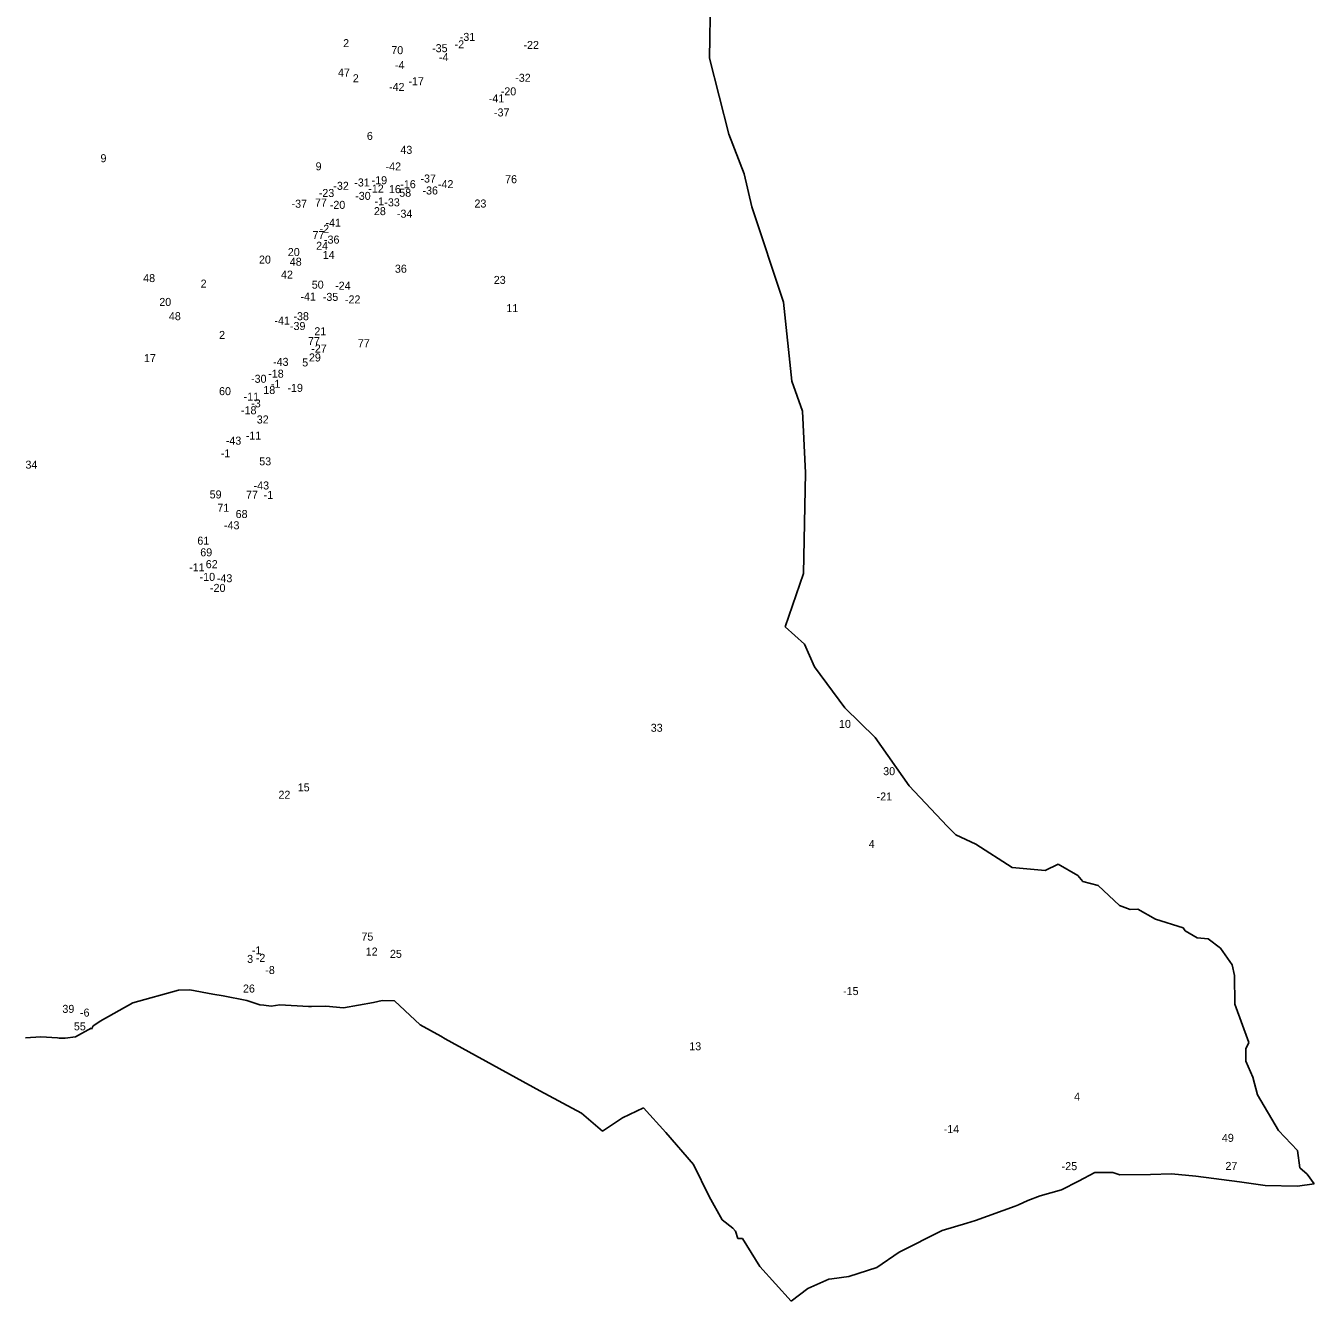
# Model space of a CAD drawing. Extents: x -774899 to -771684, y -969532 to -966391.
# Drawn here: x -773293 to -771684, y -969532 to -967940 of the extents above; entities that cross this region are included whole.
import ezdxf

# ---------------------------------------------------------------- set-up
doc = ezdxf.new("R2010")
doc.units = 0
doc.layers.add('Vrstva 13', color=7, linetype='Continuous')
doc.layers.add('Vrstva 24', color=7, linetype='Continuous')

msp = doc.modelspace()

# ---------------------------------------------------------------- linework, layer by layer
at = {"layer": 'Vrstva 13'}
for p, q in [((-772437.19, -967872.16), (-772439.45, -967979.8)), ((-772439.45, -967979.8), (-772415.04, -968074.78)), ((-772415.04, -968074.78), (-772396.05, -968124.53)), ((-772396.05, -968124.53), (-772386.56, -968165.69)), ((-772386.56, -968165.69), (-772346.77, -968284.64)), ((-772346.77, -968284.64), (-772336.37, -968383.23)), ((-772336.37, -968383.23), (-772323.26, -968420.77)), ((-772323.26, -968420.77), (-772319.31, -968497.55)), ((-772319.31, -968497.55), (-772321.8, -968623.5)), ((-772321.8, -968623.5), (-772344.62, -968690.22)), ((-772344.62, -968690.22), (-772320.66, -968711.7)), ((-772320.66, -968711.7), (-772308.23, -968739.97)), ((-772308.23, -968739.97), (-772270.03, -968791.08)), ((-772270.03, -968791.08), (-772232.5, -968828.16)), ((-772232.5, -968828.16), (-772190.02, -968888.54)), ((-772190.02, -968888.54), (-772142.32, -968938.74)), ((-772142.32, -968938.74), (-772131.7, -968949.82)), ((-772131.7, -968949.82), (-772106.6, -968961.35)), ((-772106.6, -968961.35), (-772061.17, -968990.75)), ((-772061.17, -968990.75), (-772019.8, -968994.14)), ((-772019.8, -968994.14), (-772003.76, -968986.22)), ((-772003.76, -968986.22), (-771979.34, -969000.46)), ((-771979.34, -969000.46), (-771973.01, -969008.15)), ((-771973.01, -969008.15), (-771953.57, -969013.13)), ((-771953.57, -969013.13), (-771926.9, -969038)), ((-771926.9, -969038), (-771913.79, -969042.98)), ((-771913.79, -969042.98), (-771904.07, -969042.52)), ((-771904.07, -969042.52), (-771882.14, -969054.96)), ((-771882.14, -969054.96), (-771847.55, -969066.04)), ((-771847.55, -969066.04), (-771845.06, -969069.44)), ((-771845.06, -969069.44), (-771829.91, -969078.49)), ((-771829.91, -969078.49), (-771816.35, -969079.62)), ((-771816.35, -969079.62), (-771800.98, -969091.38)), ((-771800.98, -969091.38), (-771786.51, -969111.96)), ((-771786.51, -969111.96), (-771783.57, -969125.53)), ((-771783.57, -969125.53), (-771783.12, -969161.03)), ((-773102.4, -969143.73), (-773159.41, -969159.5)), ((-773088.19, -969143.4), (-773102.4, -969143.73)), ((-773059.49, -969148.9), (-773088.19, -969143.4)), ((-773046.58, -969150.75), (-773059.49, -969148.9)), ((-773017.32, -969156.51), (-773046.58, -969150.75)), ((-773159.41, -969159.5), (-773200.39, -969182.61)), ((-773003.4, -969161.13), (-773017.32, -969156.51)), ((-773003.4, -969161.13), (-773000.97, -969161.95)), ((-773000.97, -969161.95), (-772995.77, -969162.34)), ((-772986.93, -969163.77), (-772995.77, -969162.34)), ((-772976.12, -969162.25), (-772986.93, -969163.77)), ((-772940.04, -969164.24), (-772976.12, -969162.25)), ((-772936.61, -969164.14), (-772940.04, -969164.24)), ((-772918.51, -969163.65), (-772936.61, -969164.14)), ((-772896.48, -969165.76), (-772918.51, -969163.65)), ((-772858.93, -969159.13), (-772896.48, -969165.76)), ((-772858.93, -969159.13), (-772848.29, -969156.56)), ((-772832.65, -969156.92), (-772848.29, -969156.56)), ((-772819.87, -969168.99), (-772832.65, -969156.92)), ((-772800.87, -969186.92), (-772819.87, -969168.99)), ((-771783.12, -969161.03), (-771765.49, -969209.2)), ((-773204.64, -969185.35), (-773209.22, -969188.39)), ((-773200.39, -969182.61), (-773204.64, -969185.35)), ((-773231.01, -969202.03), (-773211.56, -969191.33)), ((-773211.56, -969191.33), (-773211.3, -969192.34)), ((-773209.22, -969188.39), (-773211.3, -969192.34)), ((-772774.7, -969201.31), (-772800.87, -969186.92)), ((-772769.26, -969204.3), (-772774.7, -969201.31)), ((-773274.63, -969201.98), (-773293.46, -969203.4)), ((-773253.53, -969203.43), (-773274.63, -969201.98)), ((-773253.53, -969203.43), (-773251.7, -969203.67)), ((-773251.7, -969203.67), (-773245.61, -969203.86)), ((-773245.61, -969203.86), (-773243.99, -969203.61)), ((-773231.01, -969202.03), (-773243.99, -969203.61)), ((-772651.15, -969269.24), (-772769.26, -969204.3)), ((-771765.49, -969209.2), (-771769.33, -969217.11)), ((-771769.33, -969217.11), (-771769.33, -969232.49)), ((-771769.33, -969232.49), (-771760.52, -969252.39)), ((-771760.52, -969252.39), (-771754.64, -969274.32)), ((-772599.16, -969297.26), (-772651.15, -969269.24)), ((-771754.64, -969274.32), (-771728.63, -969318.87)), ((-772572.97, -969319.97), (-772599.16, -969297.26)), ((-772521.8, -969290.83), (-772547.95, -969303.03)), ((-772493.99, -969321.5), (-772521.8, -969290.83)), ((-772547.95, -969303.03), (-772572.97, -969319.97)), ((-772459.33, -969361.3), (-772493.99, -969321.5)), ((-771728.63, -969318.87), (-771704.96, -969344.14)), ((-771704.96, -969344.14), (-771702.02, -969365.51)), ((-772439.82, -969401.52), (-772459.33, -969361.3)), ((-771957.98, -969371.59), (-771978.38, -969382.13)), ((-771935.57, -969371.35), (-771957.98, -969371.59)), ((-771926.63, -969374.16), (-771935.57, -969371.35)), ((-771888.48, -969373.7), (-771926.63, -969374.16)), ((-771862.03, -969372.94), (-771888.48, -969373.7)), ((-771831.91, -969375.83), (-771862.03, -969372.94)), ((-771777.16, -969383.06), (-771831.91, -969375.83)), ((-771702.02, -969365.51), (-771692.86, -969373.32)), ((-771692.86, -969373.32), (-771683.86, -969385.69)), ((-771999.37, -969392.97), (-772026.03, -969400.57)), ((-771978.38, -969382.13), (-771999.37, -969392.97)), ((-771745.31, -969387.83), (-771777.16, -969383.06)), ((-771704.77, -969388.59), (-771745.31, -969387.83)), ((-771683.86, -969385.69), (-771704.77, -969388.59)), ((-772423.56, -969430.4), (-772439.82, -969401.52)), ((-772041.78, -969406.46), (-772053.37, -969411.59)), ((-772026.03, -969400.57), (-772041.78, -969406.46)), ((-772057.63, -969413.46), (-772107.14, -969431.33)), ((-772053.37, -969411.59), (-772057.63, -969413.46)), ((-772410.02, -969440.78), (-772423.56, -969430.4)), ((-772406.7, -969444.71), (-772410.02, -969440.78)), ((-772117.82, -969434.57), (-772148.52, -969443.89)), ((-772107.14, -969431.33), (-772117.82, -969434.57)), ((-772403.77, -969453.81), (-772406.7, -969444.71)), ((-772397.94, -969453.99), (-772403.77, -969453.81)), ((-772376.33, -969488.77), (-772397.94, -969453.99)), ((-772148.52, -969443.89), (-772202.27, -969470.71)), ((-772202.27, -969470.71), (-772230.16, -969490.12)), ((-772337.14, -969532.14), (-772376.33, -969488.77)), ((-772230.16, -969490.12), (-772265.25, -969501.24)), ((-772290.01, -969504.4), (-772316.56, -969516.18)), ((-772286.56, -969504.02), (-772290.01, -969504.4)), ((-772265.25, -969501.24), (-772286.56, -969504.02)), ((-772316.56, -969516.18), (-772337.14, -969532.14))]:
    msp.add_line(p, q, dxfattribs=at)

# ---------------------------------------------------------------- texts
at = {"layer": 'Vrstva 24'}
for s, p in [('2', (-772896.876, -967966.18)), ('-2', (-772757.63, -967967.65)), ('-31', (-772751.244, -967958.41)), ('-22', (-772671.66, -967968.44)), ('70', (-772836.725, -967974.95)), ('-35', (-772785.75, -967972.47)), ('-4', (-772777.156, -967983.68)), ('47', (-772903.321, -968002.92)), ('-4', (-772832.116, -967993.59)), ('2', (-772884.796, -968010.05)), ('-17', (-772815.344, -968013.8)), ('-32', (-772681.93, -968009.46)), ('-42', (-772839.566, -968020.91)), ('-41', (-772715.01, -968035.19)), ('-20', (-772700, -968026.4)), ('-37', (-772708.449, -968052.71)), ('6', (-772867.23, -968082.03)), ('43', (-772825.382, -968099.41)), ('9', (-773199.98, -968109.87)), ('9', (-772931.27, -968119.98)), ('-42', (-772843.886, -968120.18)), ('-32', (-772909.14, -968144.34)), ('-31', (-772882.994, -968140.17)), ('-12', (-772865.474, -968147.87)), ('-19', (-772861.268, -968137.36)), ('16', (-772839.664, -968148.5)), ('-16', (-772825.508, -968142.31)), ('-37', (-772800.319, -968135.22)), ('-42', (-772778.466, -968142.27)), ('76', (-772694.568, -968136.11)), ('77', (-772932.034, -968165.19)), ('-23', (-772927.34, -968153.29)), ('-30', (-772881.82, -968156.91)), ('-1', (-772857.654, -968163.76)), ('-33', (-772845.44, -968164.98)), ('58', (-772826.816, -968153.01)), ('-36', (-772797.774, -968150.16)), ('-37', (-772961.319, -968166.73)), ('-20', (-772913.56, -968168.11)), ('28', (-772858.426, -968175.96)), ('-34', (-772829.716, -968179.18)), ('23', (-772732.846, -968166.46)), ('-41', (-772918.94, -968190.37)), ('77', (-772935.104, -968205.72)), ('-2', (-772926.22, -968197.94)), ('-36', (-772920.814, -968211.5)), ('20', (-772966.006, -968227.07)), ('24', (-772930.672, -968219.25)), ('20', (-773002.026, -968236.44)), ('48', (-772963.552, -968239.09)), ('14', (-772922.337, -968230.57)), ('48', (-773146.662, -968259.54)), ('42', (-772974.492, -968255.24)), ('36', (-772832.22, -968247.87)), ('23', (-772708.696, -968261.85)), ('2', (-773074.926, -968266.45)), ('50', (-772936.066, -968267.77)), ('-24', (-772906.936, -968269.07)), ('20', (-773126.526, -968289.34)), ('-41', (-772950.25, -968282.63)), ('-35', (-772922.3, -968283.05)), ('-22', (-772894.6, -968286.19)), ('48', (-773114.542, -968307.1)), ('-38', (-772958.98, -968307.14)), ('11', (-772692.976, -968297.09)), ('-41', (-772982.78, -968312.67)), ('-39', (-772963.334, -968319.45)), ('21', (-772932.841, -968325.94)), ('2', (-773051.816, -968330.55)), ('77', (-772940.794, -968338.21)), ('77', (-772878.554, -968340.98)), ('29', (-772939.62, -968358.66)), ('-27', (-772936.699, -968347.53)), ('17', (-773145.67, -968359.53)), ('-43', (-772984.436, -968364.17)), ('5', (-772948.066, -968364.91)), ('-30', (-773011.93, -968385.29)), ('-18', (-772990.494, -968378.91)), ('60', (-773051.88, -968400.76)), ('18', (-772996.561, -968399.3)), ('-1', (-772987.154, -968391.59)), ('-19', (-772966.478, -968396.64)), ('-11', (-773021.189, -968407.65)), ('-3', (-773011.73, -968415.96)), ('-18', (-773024.484, -968424.6)), ('32', (-773004.806, -968436.12)), ('-43', (-773043.446, -968462.55)), ('-11', (-773018.539, -968456.23)), ('-1', (-773049.724, -968478.38)), ('34', (-773293.692, -968492.52)), ('53', (-773001.696, -968488.38)), ('-43', (-773008.716, -968518.52)), ('59', (-773063.61, -968529.7)), ('77', (-773018.224, -968530.16)), ('-1', (-772996.134, -968530.32)), ('71', (-773053.97, -968546.32)), ('68', (-773031.17, -968554.2)), ('-43', (-773045.716, -968568.23)), ('61', (-773078.974, -968587.46)), ('69', (-773075.354, -968601.98)), ('-11', (-773089.269, -968620.78)), ('62', (-773068.5, -968616.79)), ('-10', (-773076.175, -968632.65)), ('-20', (-773063.2, -968646.43)), ('-43', (-773054.626, -968634.36)), ('33', (-772512.646, -968821.07)), ('10', (-772277.491, -968816.27)), ('30', (-772222.306, -968875.28)), ('22', (-772977.686, -968904.71)), ('15', (-772953.591, -968895.46)), ('-21', (-772230.504, -968906.86)), ('4', (-772240.302, -968966.09)), ('75', (-772874.025, -969081.84)), ('3', (-773016.826, -969109.71)), ('-1', (-773010.924, -969098.98)), ('-2', (-773005.99, -969108.39)), ('12', (-772868.661, -969100.51)), ('25', (-772838.406, -969103.38)), ('-8', (-772994.12, -969123.6)), ('26', (-773022.01, -969146.71)), ('-15', (-772272.434, -969149.87)), ('39', (-773247.56, -969172.09)), ('-6', (-773225.594, -969176.72)), ('55', (-773233.256, -969193.88)), ('13', (-772464.491, -969218.77)), ('4', (-771983.782, -969281.53)), ('-14', (-772146.71, -969322.19)), ('49', (-771799.206, -969333.13)), ('-25', (-771999.35, -969368.47)), ('27', (-771794.776, -969368.2))]:
    msp.add_text(s, height=10, dxfattribs=at).set_placement(p)

doc.saveas('drawing.dxf')
